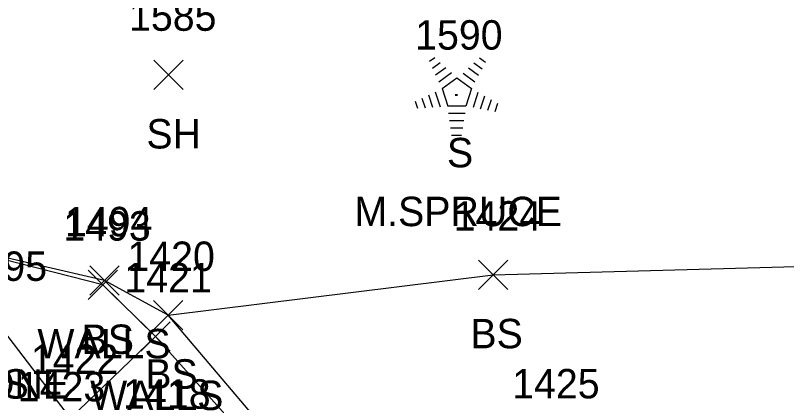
# Model space of a CAD drawing. Extents: x 1459992 to 1461532, y 647785 to 648535.
# Drawn here: x 1461373.7 to 1461426.2, y 648170.5 to 648196.8 of the extents above; entities that cross this region are included whole.
import ezdxf

# ---------------------------------------------------------------- set-up
doc = ezdxf.new("R2010")
doc.units = 0
for name, color, linetype in [('L_A', 7, 'Continuous'), ('L_C', 7, 'Continuous'), ('L_I', 7, 'Continuous'), ('L_TIC', 7, 'Continuous'), ('LELB', 7, 'Continuous'), ('LTC', 7, 'Continuous'), ('LWS', 7, 'Continuous')]:
    doc.layers.add(name, color=color, linetype=linetype)

msp = doc.modelspace()

# ---------------------------------------------------------------- linework, layer by layer
at = {"layer": 'L_TIC'}
for points in [[(1461383.139, 648191.782), (1461385.139, 648193.782)], [(1461385.139, 648191.782), (1461383.139, 648193.782)], [(1461405.228, 648178.201), (1461407.228, 648180.201)], [(1461407.228, 648178.201), (1461405.228, 648180.201)], [(1461378.778, 648177.815), (1461380.778, 648179.815)], [(1461380.778, 648177.815), (1461378.778, 648179.815)], [(1461378.666, 648177.519), (1461380.666, 648179.519)], [(1461380.666, 648177.519), (1461378.666, 648179.519)], [(1461383.114, 648175.457), (1461385.114, 648177.457)], [(1461385.114, 648175.457), (1461383.114, 648177.457)], [(1461383.114, 648175.457), (1461385.114, 648177.457)], [(1461385.114, 648175.457), (1461383.114, 648177.457)], [(1461382.255, 648174.001), (1461384.255, 648176.001)], [(1461384.255, 648174.001), (1461382.255, 648176.001)], [(1461382.255, 648174.001), (1461384.255, 648176.001)], [(1461384.255, 648174.001), (1461382.255, 648176.001)]]:
    msp.add_lwpolyline(points, dxfattribs=at)
at = {"layer": 'LELB'}
for points in [[(1461384.114, 648176.457), (1461406.228, 648179.201), (1461430.132, 648179.857), (1461446.815, 648183.64), (1461461.903, 648190.774), (1461480.327, 648203.316), (1461505.105, 648212.04)], [(1461395.776, 648145.183), (1461401.217, 648149.693), (1461402.296, 648152.589), (1461400, 648157.981), (1461396.861, 648163.276), (1461393.612, 648165.262), (1461384.114, 648176.457), (1461379.778, 648178.815), (1461366.22, 648181.937)], [(1461392.781, 648164.345), (1461389.751, 648160.577), (1461383.172, 648167.096), (1461377.464, 648169.459), (1461372.614, 648175.782)]]:
    msp.add_lwpolyline(points, dxfattribs=at)
at = {"layer": 'LTC'}
for p, q in [((1461401.887, 648193.711), (1461402.241, 648193.968)), ((1461405.285, 648193.951), (1461405.704, 648193.647)), ((1461402.096, 648193.245), (1461402.625, 648193.63)), ((1461402.306, 648192.78), (1461403.01, 648193.291)), ((1461404.543, 648193.255), (1461405.222, 648192.761)), ((1461404.914, 648193.603), (1461405.463, 648193.204)), ((1461402.515, 648192.314), (1461403.394, 648192.952)), ((1461404.172, 648192.906), (1461404.981, 648192.317)), ((1461402.74, 648191.859), (1461403.752, 648192.593)), ((1461403.752, 648192.593), (1461404.749, 648191.868)), ((1461402.74, 648191.859), (1461403.127, 648190.665)), ((1461404.749, 648191.868), (1461404.358, 648190.665)), ((1461401.375, 648191.207), (1461401.586, 648190.555)), ((1461401.83, 648191.423), (1461402.101, 648190.588)), ((1461402.285, 648191.64), (1461402.616, 648190.62)), ((1461405.186, 648191.597), (1461404.848, 648190.558)), ((1461405.631, 648191.347), (1461405.343, 648190.462)), ((1461400.919, 648190.99), (1461401.071, 648190.522)), ((1461404.358, 648190.665), (1461403.127, 648190.665)), ((1461406.075, 648191.097), (1461405.838, 648190.367)), ((1461406.52, 648190.847), (1461406.333, 648190.272)), ((1461404.319, 648190.165), (1461403.175, 648190.165)), ((1461404.235, 648189.665), (1461403.247, 648189.665)), ((1461404.152, 648189.165), (1461403.32, 648189.165)), ((1461404.068, 648188.665), (1461403.393, 648188.665))]:
    msp.add_line(p, q, dxfattribs=at)
at = {"layer": 'LWS'}
for points in [[(1461395.776, 648145.183), (1461400.322, 648150.694), (1461401.031, 648152.786), (1461398.988, 648157.264), (1461399.256, 648157.952), (1461396.519, 648162.757), (1461393.211, 648163.751), (1461392.781, 648164.345), (1461383.255, 648175.001), (1461379.666, 648178.519), (1461366.22, 648181.937), (1461358.31, 648179.355), (1461359.375, 648177.485)], [(1461383.255, 648175.001), (1461377.464, 648169.459)]]:
    msp.add_lwpolyline(points, dxfattribs=at)

# ---------------------------------------------------------------- texts
at = {"layer": 'L_A'}
for s, p in [('SH', (1461382.628, 648187.782)), ('S', (1461403.077, 648186.503)), ('BS', (1461404.669, 648174.201)), ('WALLS', (1461375.209, 648173.519)), ('BS', (1461378.219, 648173.815)), ('BS', (1461382.555, 648171.457)), ('BS', (1461382.555, 648171.457)), ('STONE', (1461368.157, 648170.782)), ('BS', (1461371.055, 648170.782)), ('WALLS', (1461378.798, 648170.001)), ('WALLS', (1461378.798, 648170.001))]:
    msp.add_text(s, height=2, dxfattribs=at).set_placement(p)
at = {"layer": 'L_C'}
msp.add_text('M.SPRUCE', height=2, dxfattribs=at).set_placement((1461396.778, 648182.503))
at = {"layer": 'L_I'}
for s, p in [('1585', (1461381.446, 648195.782)), ('1590', (1461400.912, 648194.503)), ('1494', (1461377.086, 648181.815)), ('1424', (1461403.535, 648182.201)), ('1493', (1461376.973, 648181.519)), ('1420', (1461381.335, 648179.457)), ('1420', (1461381.335, 648179.457)), ('1495', (1461369.921, 648178.782)), ('1495', (1461369.921, 648178.782)), ('1421', (1461381.129, 648178.001)), ('1421', (1461381.129, 648178.001)), ('1422', (1461374.771, 648172.459)), ('1422', (1461374.771, 648172.459)), ('1425', (1461407.513, 648170.796)), ('1423', (1461373.878, 648170.594)), ('1418', (1461381.046, 648170.096))]:
    msp.add_text(s, height=2, dxfattribs=at).set_placement(p)
at = {"layer": 'LTC'}
msp.add_text('.', height=1.037, rotation=270, dxfattribs=at).set_placement((1461403.634, 648191.607))

doc.saveas('drawing.dxf')
